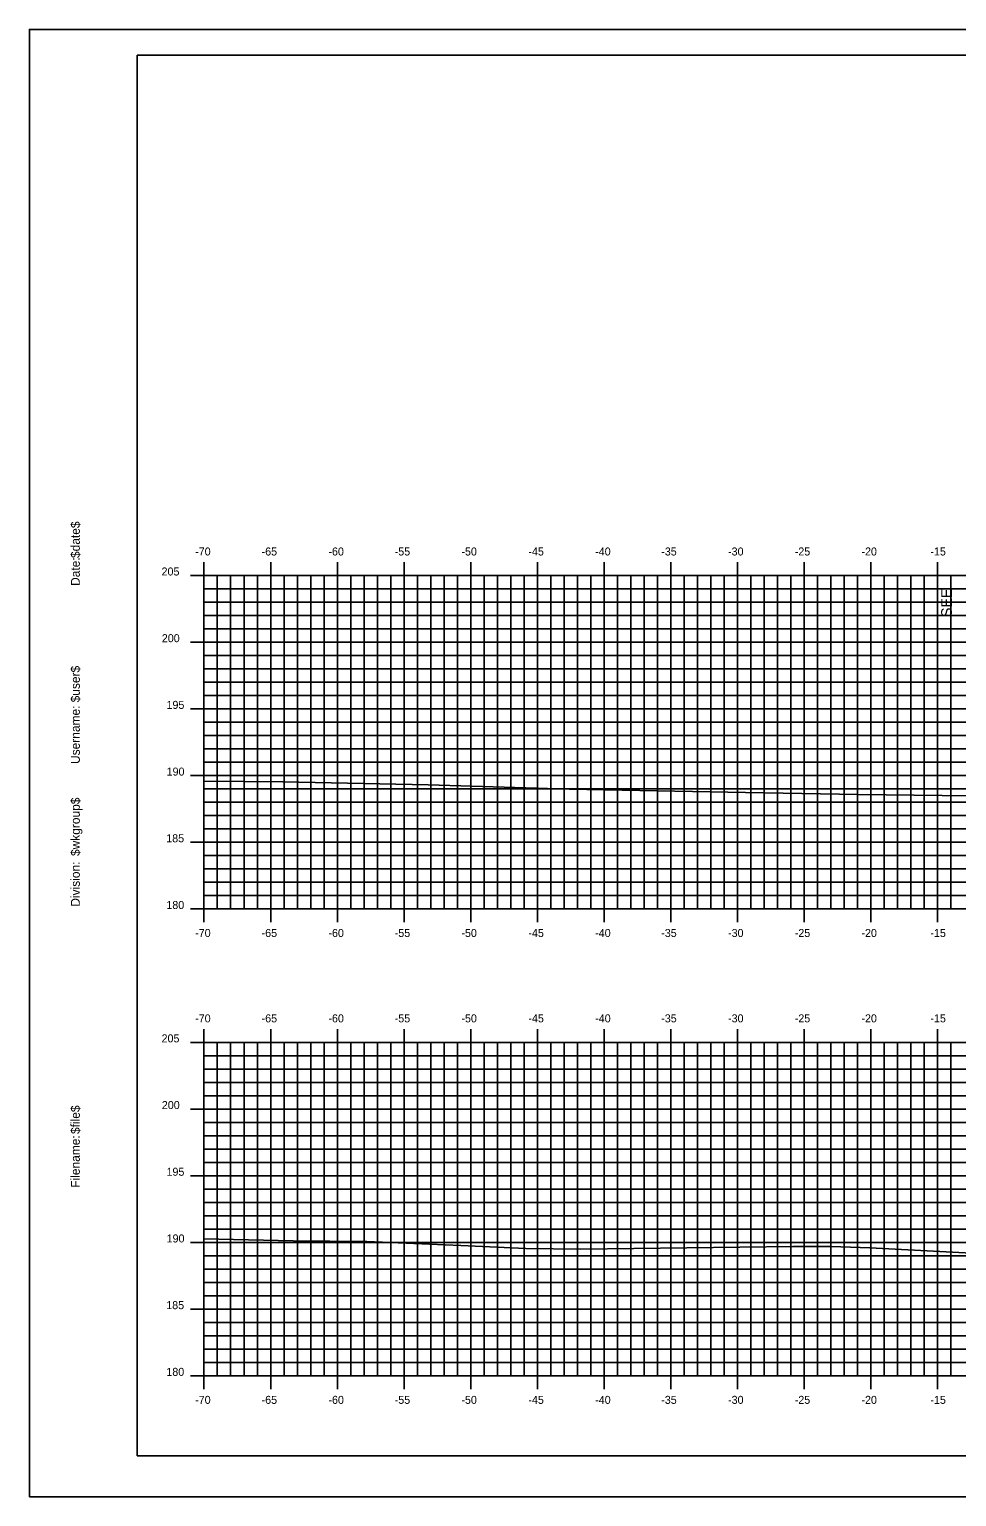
# Model space of a CAD drawing. Extents: x 1723518 to 1723690, y 459560 to 459670.
# Drawn here: x 1723517.9 to 1723587.4, y 459559.6 to 459669.6 of the extents above; entities that cross this region are included whole.
import ezdxf

# ---------------------------------------------------------------- set-up
doc = ezdxf.new("R2010")
doc.units = 0
for name, color, linetype in [('ANNOTATION', 7, 'Continuous'), ('BORDER', 7, 'Continuous'), ('H_V ANNOTATION', 7, 'Continuous'), ('MAJOR', 7, 'Continuous'), ('MINOR', 7, 'Continuous'), ('PLOT BOUNDARY', 7, 'Continuous'), ('S_Roadway_Centerline', 7, 'Continuous')]:
    doc.layers.add(name, color=color, linetype=linetype)

msp = doc.modelspace()

# ---------------------------------------------------------------- linework, layer by layer
at = {"layer": 'BORDER'}
msp.add_lwpolyline([(1723525.96, 459562.61), (1723685.96, 459562.61), (1723685.96, 459667.61), (1723525.96, 459667.61)], close=True, dxfattribs=at)
at = {"layer": 'MAJOR'}
for p, q in [((1723530.96, 459629.61), (1723530.96, 459628.61)), ((1723535.96, 459629.61), (1723535.96, 459628.61)), ((1723540.96, 459629.61), (1723540.96, 459628.61)), ((1723545.96, 459629.61), (1723545.96, 459628.61)), ((1723550.96, 459629.61), (1723550.96, 459628.61)), ((1723555.96, 459629.61), (1723555.96, 459628.61)), ((1723560.96, 459629.61), (1723560.96, 459628.61)), ((1723565.96, 459629.61), (1723565.96, 459628.61)), ((1723570.96, 459629.61), (1723570.96, 459628.61)), ((1723575.96, 459629.61), (1723575.96, 459628.61)), ((1723580.96, 459629.61), (1723580.96, 459628.61)), ((1723585.96, 459629.61), (1723585.96, 459628.61)), ((1723529.96, 459628.61), (1723530.96, 459628.61)), ((1723530.96, 459628.61), (1723670.96, 459628.61)), ((1723530.96, 459603.61), (1723530.96, 459628.61)), ((1723530.96, 459603.61), (1723530.96, 459628.61)), ((1723530.96, 459628.61), (1723670.96, 459628.61)), ((1723535.96, 459603.61), (1723535.96, 459628.61)), ((1723540.96, 459603.61), (1723540.96, 459628.61)), ((1723545.96, 459603.61), (1723545.96, 459628.61)), ((1723550.96, 459603.61), (1723550.96, 459628.61)), ((1723555.96, 459603.61), (1723555.96, 459628.61)), ((1723560.96, 459603.61), (1723560.96, 459628.61)), ((1723565.96, 459603.61), (1723565.96, 459628.61)), ((1723570.96, 459603.61), (1723570.96, 459628.61)), ((1723575.96, 459603.61), (1723575.96, 459628.61)), ((1723580.96, 459603.61), (1723580.96, 459628.61)), ((1723585.96, 459603.61), (1723585.96, 459628.61)), ((1723529.96, 459623.61), (1723530.96, 459623.61)), ((1723530.96, 459623.61), (1723670.96, 459623.61)), ((1723529.96, 459618.61), (1723530.96, 459618.61)), ((1723530.96, 459618.61), (1723670.96, 459618.61)), ((1723529.96, 459613.61), (1723530.96, 459613.61)), ((1723530.96, 459613.61), (1723670.96, 459613.61)), ((1723529.96, 459608.61), (1723530.96, 459608.61)), ((1723530.96, 459608.61), (1723670.96, 459608.61)), ((1723529.96, 459603.61), (1723530.96, 459603.61)), ((1723530.96, 459603.61), (1723670.96, 459603.61)), ((1723530.96, 459603.61), (1723670.96, 459603.61)), ((1723530.96, 459602.61), (1723530.96, 459603.61)), ((1723535.96, 459602.61), (1723535.96, 459603.61)), ((1723540.96, 459602.61), (1723540.96, 459603.61)), ((1723545.96, 459602.61), (1723545.96, 459603.61)), ((1723550.96, 459602.61), (1723550.96, 459603.61)), ((1723555.96, 459602.61), (1723555.96, 459603.61)), ((1723560.96, 459602.61), (1723560.96, 459603.61)), ((1723565.96, 459602.61), (1723565.96, 459603.61)), ((1723570.96, 459602.61), (1723570.96, 459603.61)), ((1723575.96, 459602.61), (1723575.96, 459603.61)), ((1723580.96, 459602.61), (1723580.96, 459603.61)), ((1723585.96, 459602.61), (1723585.96, 459603.61)), ((1723530.96, 459594.61), (1723530.96, 459593.61)), ((1723535.96, 459594.61), (1723535.96, 459593.61)), ((1723540.96, 459594.61), (1723540.96, 459593.61)), ((1723545.96, 459594.61), (1723545.96, 459593.61)), ((1723550.96, 459594.61), (1723550.96, 459593.61)), ((1723555.96, 459594.61), (1723555.96, 459593.61)), ((1723560.96, 459594.61), (1723560.96, 459593.61)), ((1723565.96, 459594.61), (1723565.96, 459593.61)), ((1723570.96, 459594.61), (1723570.96, 459593.61)), ((1723575.96, 459594.61), (1723575.96, 459593.61)), ((1723580.96, 459594.61), (1723580.96, 459593.61)), ((1723585.96, 459594.61), (1723585.96, 459593.61)), ((1723529.96, 459593.61), (1723530.96, 459593.61)), ((1723530.96, 459593.61), (1723670.96, 459593.61)), ((1723530.96, 459568.61), (1723530.96, 459593.61)), ((1723530.96, 459568.61), (1723530.96, 459593.61)), ((1723530.96, 459593.61), (1723670.96, 459593.61)), ((1723535.96, 459568.61), (1723535.96, 459593.61)), ((1723540.96, 459568.61), (1723540.96, 459593.61)), ((1723545.96, 459568.61), (1723545.96, 459593.61)), ((1723550.96, 459568.61), (1723550.96, 459593.61)), ((1723555.96, 459568.61), (1723555.96, 459593.61)), ((1723560.96, 459568.61), (1723560.96, 459593.61)), ((1723565.96, 459568.61), (1723565.96, 459593.61)), ((1723570.96, 459568.61), (1723570.96, 459593.61)), ((1723575.96, 459568.61), (1723575.96, 459593.61)), ((1723580.96, 459568.61), (1723580.96, 459593.61)), ((1723585.96, 459568.61), (1723585.96, 459593.61)), ((1723529.96, 459588.61), (1723530.96, 459588.61)), ((1723530.96, 459588.61), (1723670.96, 459588.61)), ((1723529.96, 459583.61), (1723530.96, 459583.61)), ((1723530.96, 459583.61), (1723670.96, 459583.61)), ((1723529.96, 459578.61), (1723530.96, 459578.61)), ((1723530.96, 459578.61), (1723670.96, 459578.61)), ((1723529.96, 459573.61), (1723530.96, 459573.61)), ((1723530.96, 459573.61), (1723670.96, 459573.61)), ((1723529.96, 459568.61), (1723530.96, 459568.61)), ((1723530.96, 459568.61), (1723670.96, 459568.61)), ((1723530.96, 459568.61), (1723670.96, 459568.61)), ((1723530.96, 459567.61), (1723530.96, 459568.61)), ((1723535.96, 459567.61), (1723535.96, 459568.61)), ((1723540.96, 459567.61), (1723540.96, 459568.61)), ((1723545.96, 459567.61), (1723545.96, 459568.61)), ((1723550.96, 459567.61), (1723550.96, 459568.61)), ((1723555.96, 459567.61), (1723555.96, 459568.61)), ((1723560.96, 459567.61), (1723560.96, 459568.61)), ((1723565.96, 459567.61), (1723565.96, 459568.61)), ((1723570.96, 459567.61), (1723570.96, 459568.61)), ((1723575.96, 459567.61), (1723575.96, 459568.61)), ((1723580.96, 459567.61), (1723580.96, 459568.61)), ((1723585.96, 459567.61), (1723585.96, 459568.61))]:
    msp.add_line(p, q, dxfattribs=at)
at = {"layer": 'MINOR'}
for p, q in [((1723531.96, 459603.61), (1723531.96, 459628.61)), ((1723532.96, 459603.61), (1723532.96, 459628.61)), ((1723533.96, 459603.61), (1723533.96, 459628.61)), ((1723534.96, 459603.61), (1723534.96, 459628.61)), ((1723536.96, 459603.61), (1723536.96, 459628.61)), ((1723537.96, 459603.61), (1723537.96, 459628.61)), ((1723538.96, 459603.61), (1723538.96, 459628.61)), ((1723539.96, 459603.61), (1723539.96, 459628.61)), ((1723541.96, 459603.61), (1723541.96, 459628.61)), ((1723542.96, 459603.61), (1723542.96, 459628.61)), ((1723543.96, 459603.61), (1723543.96, 459628.61)), ((1723544.96, 459603.61), (1723544.96, 459628.61)), ((1723546.96, 459603.61), (1723546.96, 459628.61)), ((1723547.96, 459603.61), (1723547.96, 459628.61)), ((1723548.96, 459603.61), (1723548.96, 459628.61)), ((1723549.96, 459603.61), (1723549.96, 459628.61)), ((1723551.96, 459603.61), (1723551.96, 459628.61)), ((1723552.96, 459603.61), (1723552.96, 459628.61)), ((1723553.96, 459603.61), (1723553.96, 459628.61)), ((1723554.96, 459603.61), (1723554.96, 459628.61)), ((1723556.96, 459603.61), (1723556.96, 459628.61)), ((1723557.96, 459603.61), (1723557.96, 459628.61)), ((1723558.96, 459603.61), (1723558.96, 459628.61)), ((1723559.96, 459603.61), (1723559.96, 459628.61)), ((1723561.96, 459603.61), (1723561.96, 459628.61)), ((1723562.96, 459603.61), (1723562.96, 459628.61)), ((1723563.96, 459603.61), (1723563.96, 459628.61)), ((1723564.96, 459603.61), (1723564.96, 459628.61)), ((1723566.96, 459603.61), (1723566.96, 459628.61)), ((1723567.96, 459603.61), (1723567.96, 459628.61)), ((1723568.96, 459603.61), (1723568.96, 459628.61)), ((1723569.96, 459603.61), (1723569.96, 459628.61)), ((1723571.96, 459603.61), (1723571.96, 459628.61)), ((1723572.96, 459603.61), (1723572.96, 459628.61)), ((1723573.96, 459603.61), (1723573.96, 459628.61)), ((1723574.96, 459603.61), (1723574.96, 459628.61)), ((1723576.96, 459603.61), (1723576.96, 459628.61)), ((1723577.96, 459603.61), (1723577.96, 459628.61)), ((1723578.96, 459603.61), (1723578.96, 459628.61)), ((1723579.96, 459603.61), (1723579.96, 459628.61)), ((1723581.96, 459603.61), (1723581.96, 459628.61)), ((1723582.96, 459603.61), (1723582.96, 459628.61)), ((1723583.96, 459603.61), (1723583.96, 459628.61)), ((1723584.96, 459603.61), (1723584.96, 459628.61)), ((1723586.96, 459603.61), (1723586.96, 459628.61)), ((1723530.96, 459627.61), (1723670.96, 459627.61)), ((1723530.96, 459627.61), (1723531.96, 459627.61)), ((1723530.96, 459626.61), (1723670.96, 459626.61)), ((1723530.96, 459626.61), (1723531.96, 459626.61)), ((1723530.96, 459625.61), (1723670.96, 459625.61)), ((1723530.96, 459625.61), (1723531.96, 459625.61)), ((1723530.96, 459624.61), (1723670.96, 459624.61)), ((1723530.96, 459624.61), (1723531.96, 459624.61)), ((1723530.96, 459622.61), (1723670.96, 459622.61)), ((1723530.96, 459622.61), (1723531.96, 459622.61)), ((1723530.96, 459621.61), (1723670.96, 459621.61)), ((1723530.96, 459621.61), (1723531.96, 459621.61)), ((1723530.96, 459620.61), (1723670.96, 459620.61)), ((1723530.96, 459620.61), (1723531.96, 459620.61)), ((1723530.96, 459619.61), (1723670.96, 459619.61)), ((1723530.96, 459619.61), (1723531.96, 459619.61)), ((1723530.96, 459617.61), (1723670.96, 459617.61)), ((1723530.96, 459617.61), (1723531.96, 459617.61)), ((1723530.96, 459616.61), (1723670.96, 459616.61)), ((1723530.96, 459616.61), (1723531.96, 459616.61)), ((1723530.96, 459615.61), (1723670.96, 459615.61)), ((1723530.96, 459615.61), (1723531.96, 459615.61)), ((1723530.96, 459614.61), (1723670.96, 459614.61)), ((1723530.96, 459614.61), (1723531.96, 459614.61)), ((1723530.96, 459612.61), (1723670.96, 459612.61)), ((1723530.96, 459612.61), (1723531.96, 459612.61)), ((1723530.96, 459611.61), (1723670.96, 459611.61)), ((1723530.96, 459611.61), (1723531.96, 459611.61)), ((1723530.96, 459610.61), (1723670.96, 459610.61)), ((1723530.96, 459610.61), (1723531.96, 459610.61)), ((1723530.96, 459609.61), (1723670.96, 459609.61)), ((1723530.96, 459609.61), (1723531.96, 459609.61)), ((1723530.96, 459607.61), (1723670.96, 459607.61)), ((1723530.96, 459607.61), (1723531.96, 459607.61)), ((1723530.96, 459606.61), (1723670.96, 459606.61)), ((1723530.96, 459606.61), (1723531.96, 459606.61)), ((1723530.96, 459605.61), (1723670.96, 459605.61)), ((1723530.96, 459605.61), (1723531.96, 459605.61)), ((1723530.96, 459604.61), (1723670.96, 459604.61)), ((1723530.96, 459604.61), (1723531.96, 459604.61)), ((1723531.96, 459568.61), (1723531.96, 459593.61)), ((1723532.96, 459568.61), (1723532.96, 459593.61)), ((1723533.96, 459568.61), (1723533.96, 459593.61)), ((1723534.96, 459568.61), (1723534.96, 459593.61)), ((1723536.96, 459568.61), (1723536.96, 459593.61)), ((1723537.96, 459568.61), (1723537.96, 459593.61)), ((1723538.96, 459568.61), (1723538.96, 459593.61)), ((1723539.96, 459568.61), (1723539.96, 459593.61)), ((1723541.96, 459568.61), (1723541.96, 459593.61)), ((1723542.96, 459568.61), (1723542.96, 459593.61)), ((1723543.96, 459568.61), (1723543.96, 459593.61)), ((1723544.96, 459568.61), (1723544.96, 459593.61)), ((1723546.96, 459568.61), (1723546.96, 459593.61)), ((1723547.96, 459568.61), (1723547.96, 459593.61)), ((1723548.96, 459568.61), (1723548.96, 459593.61)), ((1723549.96, 459568.61), (1723549.96, 459593.61)), ((1723551.96, 459568.61), (1723551.96, 459593.61)), ((1723552.96, 459568.61), (1723552.96, 459593.61)), ((1723553.96, 459568.61), (1723553.96, 459593.61)), ((1723554.96, 459568.61), (1723554.96, 459593.61)), ((1723556.96, 459568.61), (1723556.96, 459593.61)), ((1723557.96, 459568.61), (1723557.96, 459593.61)), ((1723558.96, 459568.61), (1723558.96, 459593.61)), ((1723559.96, 459568.61), (1723559.96, 459593.61)), ((1723561.96, 459568.61), (1723561.96, 459593.61)), ((1723562.96, 459568.61), (1723562.96, 459593.61)), ((1723563.96, 459568.61), (1723563.96, 459593.61)), ((1723564.96, 459568.61), (1723564.96, 459593.61)), ((1723566.96, 459568.61), (1723566.96, 459593.61)), ((1723567.96, 459568.61), (1723567.96, 459593.61)), ((1723568.96, 459568.61), (1723568.96, 459593.61)), ((1723569.96, 459568.61), (1723569.96, 459593.61)), ((1723571.96, 459568.61), (1723571.96, 459593.61)), ((1723572.96, 459568.61), (1723572.96, 459593.61)), ((1723573.96, 459568.61), (1723573.96, 459593.61)), ((1723574.96, 459568.61), (1723574.96, 459593.61)), ((1723576.96, 459568.61), (1723576.96, 459593.61)), ((1723577.96, 459568.61), (1723577.96, 459593.61)), ((1723578.96, 459568.61), (1723578.96, 459593.61)), ((1723579.96, 459568.61), (1723579.96, 459593.61)), ((1723581.96, 459568.61), (1723581.96, 459593.61)), ((1723582.96, 459568.61), (1723582.96, 459593.61)), ((1723583.96, 459568.61), (1723583.96, 459593.61)), ((1723584.96, 459568.61), (1723584.96, 459593.61)), ((1723586.96, 459568.61), (1723586.96, 459593.61)), ((1723530.96, 459592.61), (1723670.96, 459592.61)), ((1723530.96, 459592.61), (1723531.96, 459592.61)), ((1723530.96, 459591.61), (1723670.96, 459591.61)), ((1723530.96, 459591.61), (1723531.96, 459591.61)), ((1723530.96, 459590.61), (1723670.96, 459590.61)), ((1723530.96, 459590.61), (1723531.96, 459590.61)), ((1723530.96, 459589.61), (1723670.96, 459589.61)), ((1723530.96, 459589.61), (1723531.96, 459589.61)), ((1723530.96, 459587.61), (1723670.96, 459587.61)), ((1723530.96, 459587.61), (1723531.96, 459587.61)), ((1723530.96, 459586.61), (1723670.96, 459586.61)), ((1723530.96, 459586.61), (1723531.96, 459586.61)), ((1723530.96, 459585.61), (1723670.96, 459585.61)), ((1723530.96, 459585.61), (1723531.96, 459585.61)), ((1723530.96, 459584.61), (1723670.96, 459584.61)), ((1723530.96, 459584.61), (1723531.96, 459584.61)), ((1723530.96, 459582.61), (1723670.96, 459582.61)), ((1723530.96, 459582.61), (1723531.96, 459582.61)), ((1723530.96, 459581.61), (1723670.96, 459581.61)), ((1723530.96, 459581.61), (1723531.96, 459581.61)), ((1723530.96, 459580.61), (1723670.96, 459580.61)), ((1723530.96, 459580.61), (1723531.96, 459580.61)), ((1723530.96, 459579.61), (1723670.96, 459579.61)), ((1723530.96, 459579.61), (1723531.96, 459579.61)), ((1723530.96, 459577.61), (1723670.96, 459577.61)), ((1723530.96, 459577.61), (1723531.96, 459577.61)), ((1723530.96, 459576.61), (1723670.96, 459576.61)), ((1723530.96, 459576.61), (1723531.96, 459576.61)), ((1723530.96, 459575.61), (1723670.96, 459575.61)), ((1723530.96, 459575.61), (1723531.96, 459575.61)), ((1723530.96, 459574.61), (1723670.96, 459574.61)), ((1723530.96, 459574.61), (1723531.96, 459574.61)), ((1723530.96, 459572.61), (1723670.96, 459572.61)), ((1723530.96, 459572.61), (1723531.96, 459572.61)), ((1723530.96, 459571.61), (1723670.96, 459571.61)), ((1723530.96, 459571.61), (1723531.96, 459571.61)), ((1723530.96, 459570.61), (1723670.96, 459570.61)), ((1723530.96, 459570.61), (1723531.96, 459570.61)), ((1723530.96, 459569.61), (1723670.96, 459569.61)), ((1723530.96, 459569.61), (1723531.96, 459569.61))]:
    msp.add_line(p, q, dxfattribs=at)
at = {"layer": 'PLOT BOUNDARY'}
msp.add_lwpolyline([(1723517.87, 459559.55), (1723687.87, 459559.55), (1723687.87, 459669.55), (1723517.87, 459669.55)], close=True, dxfattribs=at)
at = {"layer": 'S_Roadway_Centerline'}
for points in [[(1723530.96, 459613.18), (1723536.86, 459613.13), (1723547.76, 459612.91), (1723558.35, 459612.59), (1723571.57, 459612.33), (1723580, 459612.19), (1723588.4, 459612.08), (1723596.68, 459611.63), (1723599.86, 459611.51), (1723603.01, 459611.42), (1723621.96, 459610.85), (1723624.42, 459610.74), (1723645.75, 459610.23), (1723646.2, 459610.21), (1723657.78, 459609.53), (1723669.48, 459609.37), (1723670.49, 459609.36), (1723670.96, 459609.33)], [(1723530.96, 459578.87), (1723537.65, 459578.72), (1723543.16, 459578.68), (1723550.22, 459578.37), (1723555.1, 459578.15), (1723559.21, 459578.11), (1723575.11, 459578.31), (1723577.98, 459578.31), (1723580.88, 459578.21), (1723599.94, 459577.21), (1723600.89, 459577.15), (1723601.03, 459577.15), (1723601.18, 459577.14), (1723613.21, 459576.72), (1723624.14, 459576.44), (1723625.46, 459576.39), (1723626.96, 459576.39), (1723646.41, 459576.02), (1723650.96, 459575.89), (1723666.64, 459575.43), (1723670.6, 459575.34), (1723670.96, 459575.31)]]:
    msp.add_lwpolyline(points, dxfattribs=at)

# ---------------------------------------------------------------- texts
at = {"layer": 'ANNOTATION'}
msp.add_text('SEE', height=0.8, rotation=90, dxfattribs=at).set_placement((1723587.03, 459625.49))
at = {"layer": 'BORDER'}
for s, p in [('$date$', (1723521.65, 459629.92)), ('Date:', (1723521.65, 459627.83)), ('$user$', (1723521.65, 459619.1)), ('Username:', (1723521.65, 459614.48)), ('$wkgroup$', (1723521.65, 459607.58)), ('Division:', (1723521.65, 459603.78)), ('$file$', (1723521.65, 459586.74)), ('Filename:', (1723521.65, 459582.71))]:
    msp.add_text(s, height=0.67, rotation=90, dxfattribs=at).set_placement(p)
at = {"layer": 'H_V ANNOTATION'}
for s, p in [('-70', (1723530.3, 459630.11)), ('-65', (1723535.28, 459630.11)), ('-60', (1723540.29, 459630.11)), ('-55', (1723545.26, 459630.11)), ('-50', (1723550.26, 459630.11)), ('-45', (1723555.28, 459630.11)), ('-40', (1723560.29, 459630.11)), ('-35', (1723565.24, 459630.11)), ('-30', (1723570.25, 459630.11)), ('-25', (1723575.25, 459630.11)), ('-20', (1723580.25, 459630.11)), ('-15', (1723585.42, 459630.11)), ('205', (1723527.78, 459628.61)), ('200', (1723527.8, 459623.61)), ('195', (1723528.15, 459618.61)), ('190', (1723528.16, 459613.61)), ('185', (1723528.13, 459608.61)), ('180', (1723528.14, 459603.61)), ('-70', (1723530.3, 459601.51)), ('-65', (1723535.28, 459601.51)), ('-60', (1723540.29, 459601.51)), ('-55', (1723545.26, 459601.51)), ('-50', (1723550.26, 459601.51)), ('-45', (1723555.28, 459601.51)), ('-40', (1723560.29, 459601.51)), ('-35', (1723565.24, 459601.51)), ('-30', (1723570.25, 459601.51)), ('-25', (1723575.25, 459601.51)), ('-20', (1723580.25, 459601.51)), ('-15', (1723585.42, 459601.51)), ('-70', (1723530.3, 459595.11)), ('-65', (1723535.28, 459595.11)), ('-60', (1723540.29, 459595.11)), ('-55', (1723545.26, 459595.11)), ('-50', (1723550.26, 459595.11)), ('-45', (1723555.28, 459595.11)), ('-40', (1723560.29, 459595.11)), ('-35', (1723565.24, 459595.11)), ('-30', (1723570.25, 459595.11)), ('-25', (1723575.25, 459595.11)), ('-20', (1723580.25, 459595.11)), ('-15', (1723585.42, 459595.11)), ('205', (1723527.78, 459593.61)), ('200', (1723527.8, 459588.61)), ('195', (1723528.15, 459583.61)), ('190', (1723528.16, 459578.61)), ('185', (1723528.13, 459573.61)), ('180', (1723528.14, 459568.61)), ('-70', (1723530.3, 459566.51)), ('-65', (1723535.28, 459566.51)), ('-60', (1723540.29, 459566.51)), ('-55', (1723545.26, 459566.51)), ('-50', (1723550.26, 459566.51)), ('-45', (1723555.28, 459566.51)), ('-40', (1723560.29, 459566.51)), ('-35', (1723565.24, 459566.51)), ('-30', (1723570.25, 459566.51)), ('-25', (1723575.25, 459566.51)), ('-20', (1723580.25, 459566.51)), ('-15', (1723585.42, 459566.51))]:
    msp.add_text(s, height=0.6, dxfattribs=at).set_placement(p)
at = {"layer": 'MAJOR'}
for p in [(1723530.96, 459603.61), (1723530.96, 459568.61)]:
    msp.add_text('-', height=0.006, dxfattribs=at).set_placement(p)

doc.saveas('drawing.dxf')
